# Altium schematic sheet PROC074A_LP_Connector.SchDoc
size 431 x 279 mm; Date: Not shown in title block; ApprovedBy: Not shown in title block; CheckedBy: Not shown in title block; Author: Not shown in title block; CompanyName: Not shown in title block; Engineer: Not shown in title block; Organization: Not shown in title block; Address1: Not shown in title block; Address2: Not shown in title block; Address3: Not shown in title block; Address4: Not shown in title block; DocumentNumber: 1; Revision: Use project parameter SCH_Rev; SheetNumber: 8; SheetTotal: 22; PageSetup: Record=PageOptions¦CenterHorizontal=True¦CenterVertical=True¦PrintScale=1.00¦XCorrection=1.00¦YCorrection=1.00¦PrintKind=0¦BorderSize=5000000¦LeftOffset=0¦BottomOffset=0¦Orientation=2¦PaperLength=1000¦PaperWidth=1000¦Scale=100¦PaperSource=15¦PrintQuality=600¦MediaType=1¦DitherType=10¦PaperKind=Letter¦PrintScaleMode=1
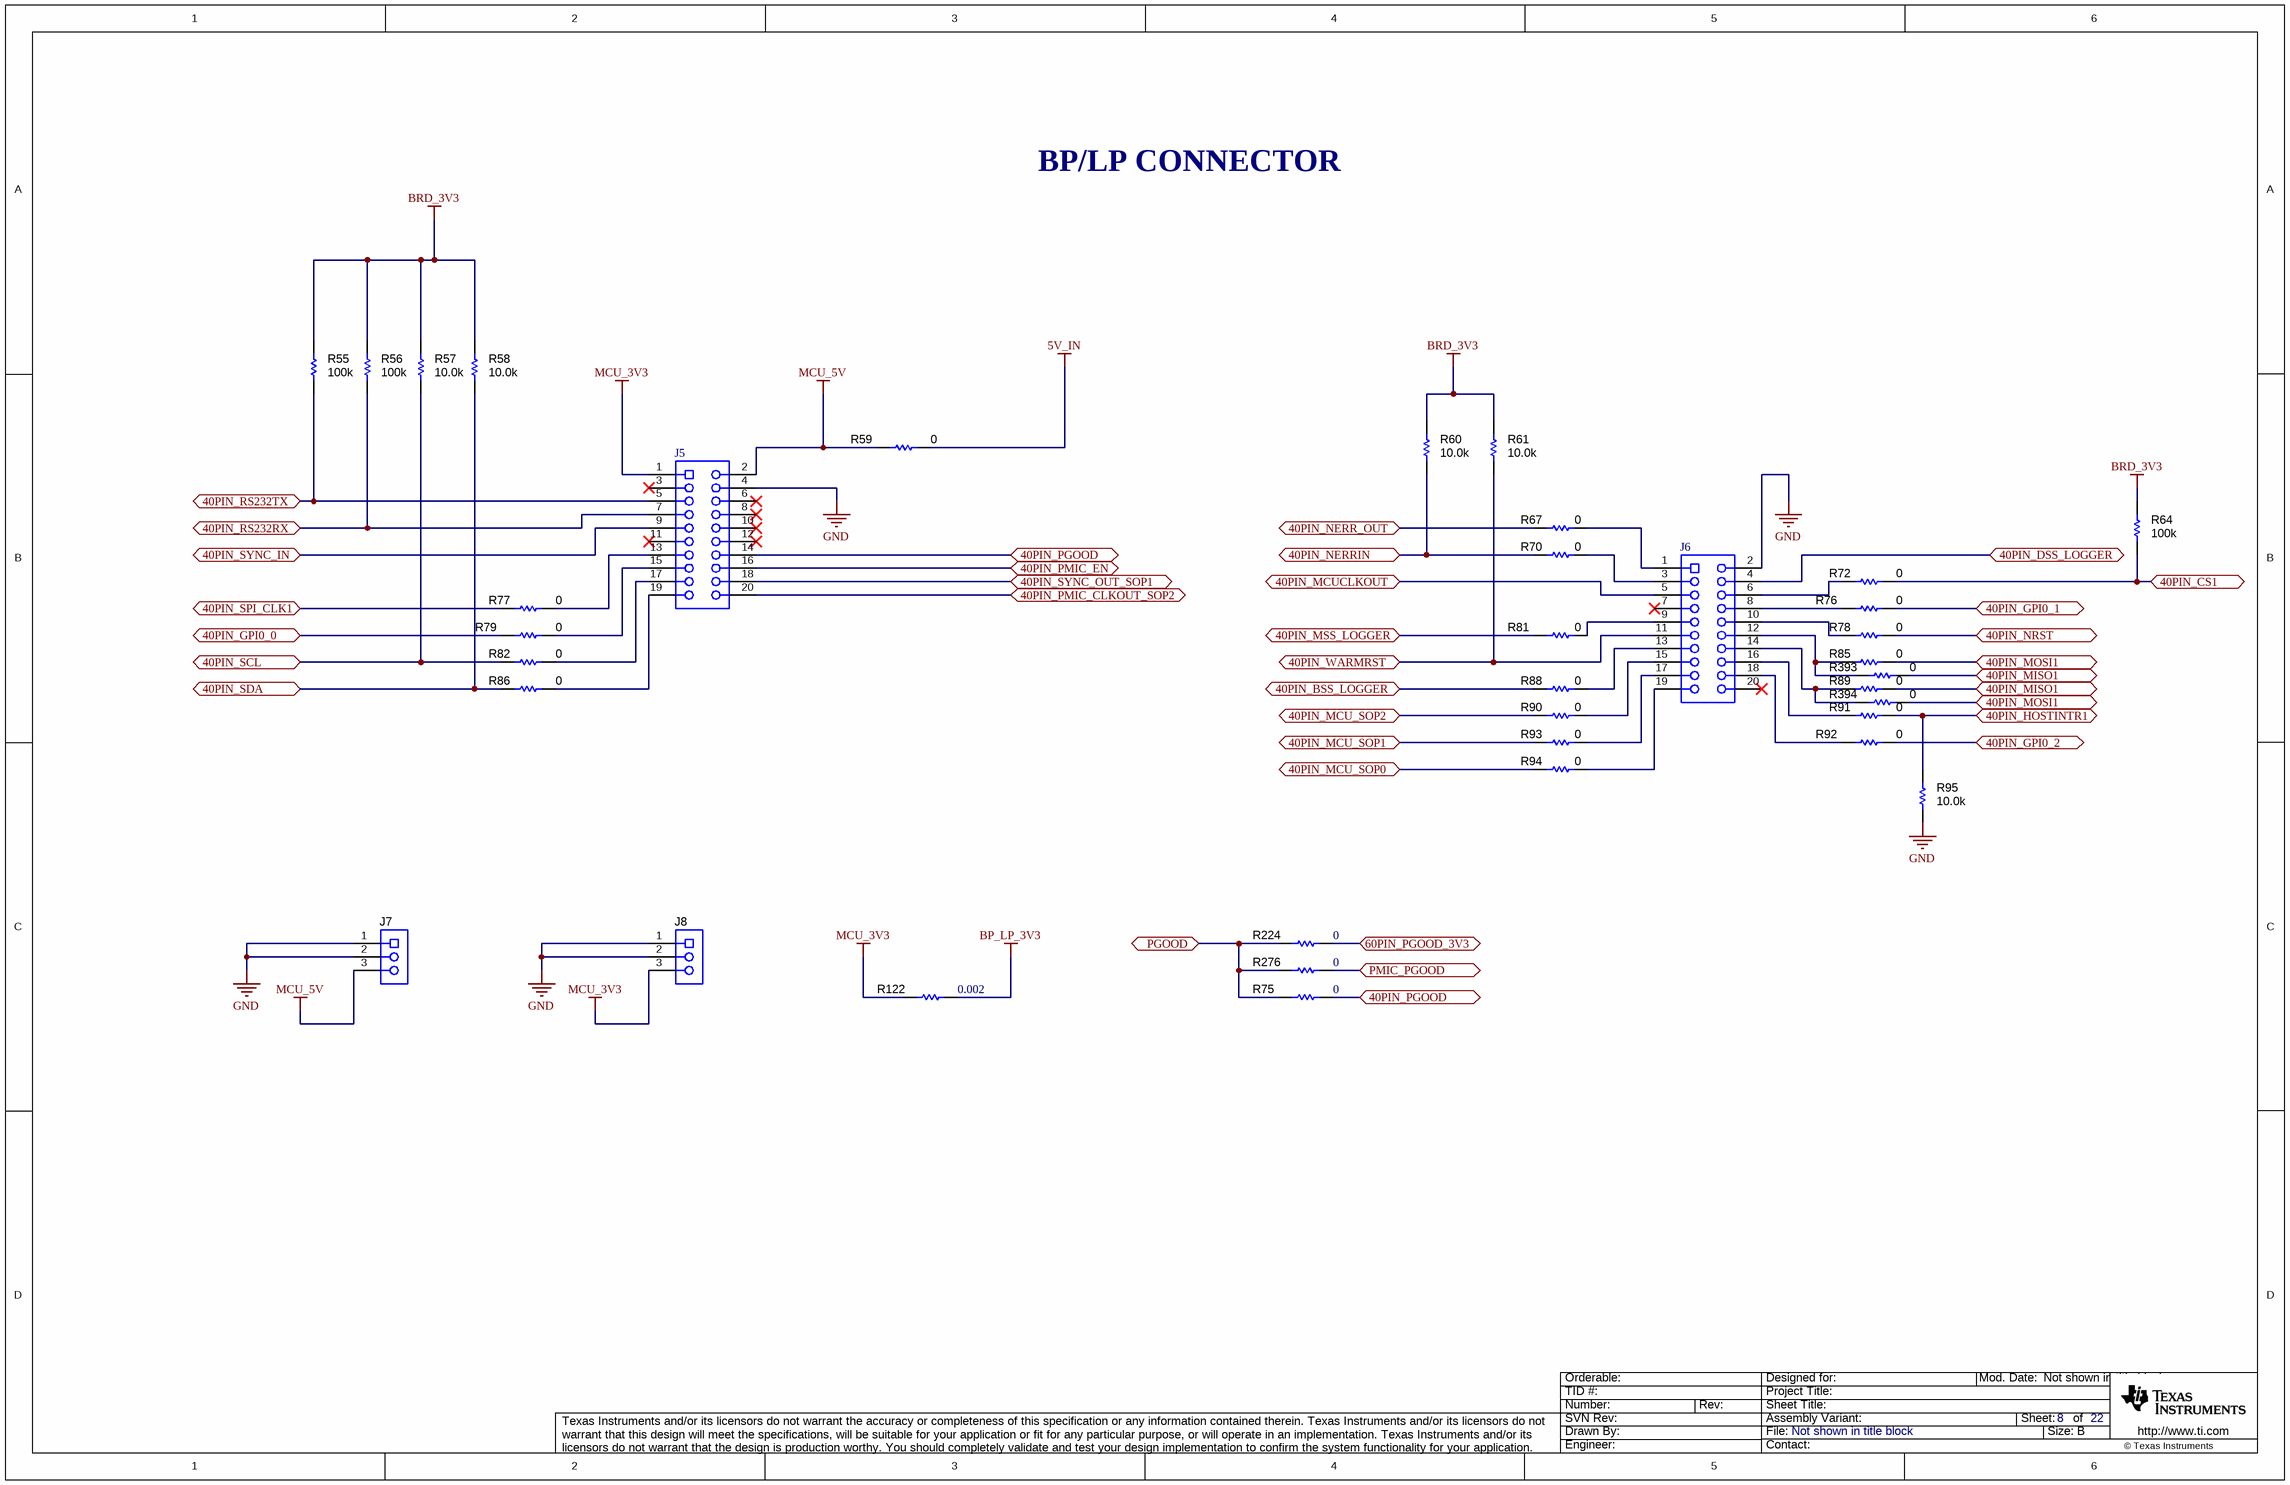
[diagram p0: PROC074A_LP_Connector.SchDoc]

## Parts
J5  SSM-110-S-DV  [Samtec_SSM-110-x-DV]  (value not drawn)
J6  SSM-110-S-DV  [Samtec_SSM-110-x-DV]  (value not drawn)
J7  SSM-103-S-SV  [Samtec_SSM-103-x-SV]  (value not drawn)
J8  SSM-103-S-SV  [Samtec_SSM-103-x-SV]  (value not drawn)
R55  ValueDisplayed: 100k  [0402L]  (hidden comment: CRCW0402100KFKED)
R56  ValueDisplayed: 100k  [0402L]  (hidden comment: CRCW0402100KFKED)
R57  ValueDisplayed: 10.0k  [0402L]  (hidden comment: CRCW040210K0FKED)
R58  ValueDisplayed: 10.0k  [0402L]  (hidden comment: CRCW040210K0FKED)
R59  ValueDisplayed: 0  [2010]  (hidden comment: CRCW20100000Z0EF)
R60  ValueDisplayed: 10.0k  [0402L]  (hidden comment: CRCW040210K0FKED)
R61  ValueDisplayed: 10.0k  [0402L]  (hidden comment: CRCW040210K0FKED)
R64  ValueDisplayed: 100k  [0402L]  (hidden comment: CRCW0402100KFKED)
R67  ValueDisplayed: 0  [0201_Silk]  (hidden comment: CRCW02010000Z0ED)
R70  ValueDisplayed: 0  [0201_Silk]  (hidden comment: CRCW02010000Z0ED)
R72  ValueDisplayed: 0  [0201_Silk]  (hidden comment: CRCW02010000Z0ED)
R75  ValueDisplayed: 0  [0402]  (hidden comment: ERJ-2GE0R00X)
R76  ValueDisplayed: 0  [0201_Silk]  (hidden comment: CRCW02010000Z0ED)
R77  ValueDisplayed: 0  [0201_Silk]  (hidden comment: CRCW02010000Z0ED)
R78  ValueDisplayed: 0  [0201_Silk]  (hidden comment: CRCW02010000Z0ED)
R79  ValueDisplayed: 0  [0201_Silk]  (hidden comment: CRCW02010000Z0ED)
R81  ValueDisplayed: 0  [0201_Silk]  (hidden comment: CRCW02010000Z0ED)
R82  ValueDisplayed: 0  [0201_Silk]  (hidden comment: CRCW02010000Z0ED)
R85  ValueDisplayed: 0  [0201_Silk]  (hidden comment: CRCW02010000Z0ED)
R86  ValueDisplayed: 0  [0201_Silk]  (hidden comment: CRCW02010000Z0ED)
R88  ValueDisplayed: 0  [0201_Silk]  (hidden comment: CRCW02010000Z0ED)
R89  ValueDisplayed: 0  [0201_Silk]  (hidden comment: CRCW02010000Z0ED)
R90  ValueDisplayed: 0  [0201_Silk]  (hidden comment: CRCW02010000Z0ED)
R91  ValueDisplayed: 0  [0201_Silk]  (hidden comment: CRCW02010000Z0ED)
R92  ValueDisplayed: 0  [0201_Silk]  (hidden comment: CRCW02010000Z0ED)
R93  ValueDisplayed: 0  [0201_Silk]  (hidden comment: CRCW02010000Z0ED)
R94  ValueDisplayed: 0  [0201_Silk]  (hidden comment: CRCW02010000Z0ED)
R95  ValueDisplayed: 10.0k  [0402L]  (hidden comment: CRCW040210K0FKED)
R122  ValueDisplayed: 0.002  [1206]  (hidden comment: PMR18EZPFV2L00)
R224  ValueDisplayed: 0  [0402]  (hidden comment: ERJ-2GE0R00X)
R276  ValueDisplayed: 0  [0402]  (hidden comment: ERJ-2GE0R00X)
R393  ValueDisplayed: 0  [0201_Silk]  (hidden comment: CRCW02010000Z0ED)
R394  ValueDisplayed: 0  [0201_Silk]  (hidden comment: CRCW02010000Z0ED)

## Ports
40PIN_BSS_LOGGER, 40PIN_CS1, 40PIN_DSS_LOGGER, 40PIN_GPI0_0, 40PIN_GPI0_1, 40PIN_GPI0_2, 40PIN_HOSTINTR1, 40PIN_MCU_SOP0, 40PIN_MCU_SOP1, 40PIN_MCU_SOP2, 40PIN_MCUCLKOUT, 40PIN_MISO1, 40PIN_MOSI1, 40PIN_MSS_LOGGER, 40PIN_NERR_OUT, 40PIN_NERRIN, 40PIN_NRST, 40PIN_PGOOD, 40PIN_PMIC_CLKOUT_SOP2, 40PIN_PMIC_EN, 40PIN_RS232RX, 40PIN_RS232TX, 40PIN_SCL, 40PIN_SDA, 40PIN_SPI_CLK1, 40PIN_SYNC_IN, 40PIN_SYNC_OUT_SOP1, 40PIN_WARMRST, 60PIN_PGOOD_3V3, PGOOD, PMIC_PGOOD

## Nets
5V_IN: R59.2
BP_LP_3V3: R122.2
BRD_3V3: R55.2 R56.2 R57.2 R58.2 R60.2 R61.2 R64.2
GND: J5.4 J6.2 J7.1 J7.2 J8.1 J8.2 R95.1
MCU_3V3: J5.1 J8.3 R122.1
MCU_5V: J5.2 J7.3 R59.1
40PIN_BSS_LOGGER: R88.1 ; port 40PIN_BSS_LOGGER
40PIN_CS1: R64.1 R72.2 ; port 40PIN_CS1
40PIN_DSS_LOGGER: J6.4 ; port 40PIN_DSS_LOGGER
40PIN_GPI0_0: R79.1 ; port 40PIN_GPI0_0
40PIN_GPI0_1: R76.2 ; port 40PIN_GPI0_1
40PIN_GPI0_2: R92.2 ; port 40PIN_GPI0_2
40PIN_HOSTINTR1: R91.2 R95.2 ; port 40PIN_HOSTINTR1
40PIN_MCU_SOP0: R94.1 ; port 40PIN_MCU_SOP0
40PIN_MCU_SOP1: R93.1 ; port 40PIN_MCU_SOP1
40PIN_MCU_SOP2: R90.1 ; port 40PIN_MCU_SOP2
40PIN_MCUCLKOUT: J6.5 ; port 40PIN_MCUCLKOUT
40PIN_MISO1: R89.2 R393.2 ; port 40PIN_MISO1
40PIN_MOSI1: R85.2 R394.2 ; port 40PIN_MOSI1
40PIN_MSS_LOGGER: R81.1 ; port 40PIN_MSS_LOGGER
40PIN_NERR_OUT: R67.1 ; port 40PIN_NERR_OUT
40PIN_NERRIN: R60.1 R70.1 ; port 40PIN_NERRIN
40PIN_NRST: R78.2 ; port 40PIN_NRST
40PIN_PGOOD: J5.14 R75.2 ; port 40PIN_PGOOD
40PIN_PMIC_CLKOUT_SOP2: J5.20 ; port 40PIN_PMIC_CLKOUT_SOP2
40PIN_PMIC_EN: J5.16 ; port 40PIN_PMIC_EN
40PIN_RS232RX: J5.7 R56.1 ; port 40PIN_RS232RX
40PIN_RS232TX: J5.5 R55.1 ; port 40PIN_RS232TX
40PIN_SCL: R57.1 R82.1 ; port 40PIN_SCL
40PIN_SDA: R58.1 R86.1 ; port 40PIN_SDA
40PIN_SPI_CLK1: R77.1 ; port 40PIN_SPI_CLK1
40PIN_SYNC_IN: J5.9 ; port 40PIN_SYNC_IN
40PIN_SYNC_OUT_SOP1: J5.18 ; port 40PIN_SYNC_OUT_SOP1
40PIN_WARMRST: J6.11 R61.1 ; port 40PIN_WARMRST
60PIN_PGOOD_3V3: R224.2 ; port 60PIN_PGOOD_3V3
PGOOD: R75.1 R224.1 R276.1 ; port PGOOD
PMIC_PGOOD: R276.2 ; port PMIC_PGOOD
NetJ5_13: J5.13 R77.2
NetJ5_15: J5.15 R79.2
NetJ5_17: J5.17 R82.2
NetJ5_19: J5.19 R86.2
NetJ6_1: J6.1 R67.2
NetJ6_3: J6.3 R70.2
NetJ6_6: J6.6 R72.1
NetJ6_8: J6.8 R76.1
NetJ6_9: J6.9 R81.2
NetJ6_10: J6.10 R78.1
NetJ6_12: J6.12 R85.1 R393.1
NetJ6_13: J6.13 R88.2
NetJ6_14: J6.14 R89.1 R394.1
NetJ6_15: J6.15 R90.2
NetJ6_16: J6.16 R91.1
NetJ6_17: J6.17 R93.2
NetJ6_18: J6.18 R92.1
NetJ6_19: J6.19 R94.2

Not connected (* = marked no-connect by the designer): J5 3* 6* 8* 10* 11* 12*; J6 7* 20*

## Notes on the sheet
- BP/LP CONNECTOR

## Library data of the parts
J5 J6 = CMP-0078182-1: Receptacle, 2.54mm, 10x2, Gold with Tin tail, SMT; Manufacturer: Samtec; Pitch_mm: 2.54; Gender: Female; Cert_CSA: Y; Voltage_V: 405V; Current_A: 5.2A; Row_Count: 2; CompType: Socket Strip
J7 J8 = CMP-0078183-1: Receptacle, 2.54mm, 3x1, Gold with Tin tail, SMT; Manufacturer: Samtec; Pitch_mm: 2.54; Gender: Female; Cert_CSA: Y; Voltage_V: 405V; Current_A: 5.2A; Row_Count: 1; CompType: Socket Strip
R55 R56 R64 = CMP-0025950-2: RES, 100 k, 1%, 0.063 W, 0402; Manufacturer: Vishay-Dale; Power_W: 63mW; TempCo: 100 ppm/C; U/M: EA; Value: 100k; EIA_Code: E96; SizeX_mm: 1; SizeY_mm: 0.5; SizeZ_mm: 0.6; Value2: 0.063W; CompType: Resistor; VDC_V: 50V; AEC Category: Q200; INSTALLATION: DNP
R57 R58 R60 R61 R95 = CMP-0025958-2: RES, 10.0 k, 1%, 0.063 W, 0402; Manufacturer: Vishay-Dale; Power_W: 63mW; TempCo: 100 ppm/C; Value_Code: 10k0; U/M: EA; Value: 10.0k; EIA_Code: E96; Res_ohm: 10k; SizeX_mm: 1; SizeY_mm: 0.5; SizeZ_mm: 0.6; Value2: 0.063W; CompType: Resistor; VDC_V: 50V; AEC Category: Q200; INSTALLATION: DNP
R59 = CMP-0016044-2: RES, 0, 5%, 0.75 W, AEC-Q200 Grade 0, 2010; Manufacturer: Vishay-Dale; Power_W: 750mW; TempCo: ppm/C; Value_Code: 0000; U/M: EA; Value: 0; EIA_Code: E24; SizeX_mm: 5; SizeY_mm: 2.5; SizeZ_mm: 1.66; Value2: 0.75W; SizeArea_mm2: 12.5; CompType: Resistor; AEC Qualified: Y; AEC Category: Q200; INSTALLATION: DNP
R67 R70 R72 R88 R90 R93 R94 = CMP-0027008-3: RES, 0, 5%, 0.05 W, 0201; Manufacturer: Vishay-Dale; Power_W: 50mW; TempCo: ppm/C; Value_Code: 0000; U/M: EA; Value: 0; EIA_Code: E24; SizeX_mm: 0.6; SizeY_mm: 0.3; SizeZ_mm: 0.26; Value2: 0.05W; SizeArea_mm2: 0.18; CompType: Resistor; AEC Qualified: N; AEC Category: Q200
R75 R276 = CMP-0026992-3: RES, 0, 5%, 0.1 W, AEC-Q200 Grade 0, 0402; Manufacturer: Panasonic; Power_W: 100mW; TempCo: 600 ppm/C; Value_Code: 0000; Value: 0; EIA_Code: E24; SizeX_mm: 1; SizeY_mm: 0.5; SizeZ_mm: 0.6; Value2: 0.1W; CompType: Resistor; AEC Qualified: Y; VDC_V: 50V; AEC Category: Q200; SizeAreaWB_mm2: 3; INSTALLATION: DNP
R76 R79 R81 R92 R393 R394 = CMP-0027008-3: RES, 0, 5%, 0.05 W, 0201; Manufacturer: Vishay-Dale; Power_W: 50mW; TempCo: ppm/C; Value_Code: 0000; U/M: EA; Value: 0; EIA_Code: E24; SizeX_mm: 0.6; SizeY_mm: 0.3; SizeZ_mm: 0.26; Value2: 0.05W; SizeArea_mm2: 0.18; CompType: Resistor; AEC Qualified: N; AEC Category: Q200; INSTALLATION: DNP
R77 R78 R82 R85 R86 R89 R91 = CMP-0027008-3: RES, 0, 5%, 0.05 W, 0201; Manufacturer: Vishay-Dale; Power_W: 50mW; TempCo: ppm/C; Value_Code: 0000; U/M: EA; Value: 0; EIA_Code: E24; SizeX_mm: 0.6; SizeY_mm: 0.3; SizeZ_mm: 0.26; Value2: 0.05W; SizeArea_mm2: 0.18; AEC Qualified: N; AEC Category: Q200
R122 = CMP-0081623-1: RES, 0.002, 1%, 1 W, AEC-Q200 Grade 0, 1206; Manufacturer: Rohm; Value_Code: 2L000; SizeAreaWB_mm2: 10.92; SizeArea_mm2: 5.12; AEC Qualified: Y; AEC Category: Q200; Res_ohm: 2m; Value: 0.002; SizeZ_mm: 1.35; Green_REACh: Incomplete; TempCo: 100 ppm/C; AEC Grade: 0; Power_W: 1W; SizeY_mm: 1.6; Green_Lifecycle: Active; CompType: Resistor; SizeX_mm: 3.2; INSTALLATION: DNP
R224 = CMP-0026992-3: RES, 0, 5%, 0.1 W, AEC-Q200 Grade 0, 0402; Manufacturer: Panasonic; Power_W: 100mW; TempCo: 600 ppm/C; Value_Code: 0000; Value: 0; EIA_Code: E24; SizeX_mm: 1; SizeY_mm: 0.5; SizeZ_mm: 0.6; Value2: 0.1W; AEC Qualified: Y; VDC_V: 50V; AEC Category: Q200; SizeAreaWB_mm2: 3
